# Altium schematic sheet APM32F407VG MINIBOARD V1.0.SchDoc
size A3; Organization: Altium Limited; Address1: 3 Minna Close; Address2: Belrose; Address3: NSW 2085; Address4: Australia; PageSetup: Record=PageOptions¦CenterHorizontal=True¦CenterVertical=True¦PrintScale=0.71¦XCorrection=1.00¦YCorrection=1.00¦PrintKind=0¦BorderSize=5000000¦LeftOffset=0¦BottomOffset=0¦Orientation=2¦PaperLength=1000¦PaperWidth=1000¦Scale=100¦PaperSource=7¦PrintQuality=-4¦MediaType=1¦DitherType=10¦PaperKind=A4¦PrintScaleMode=1
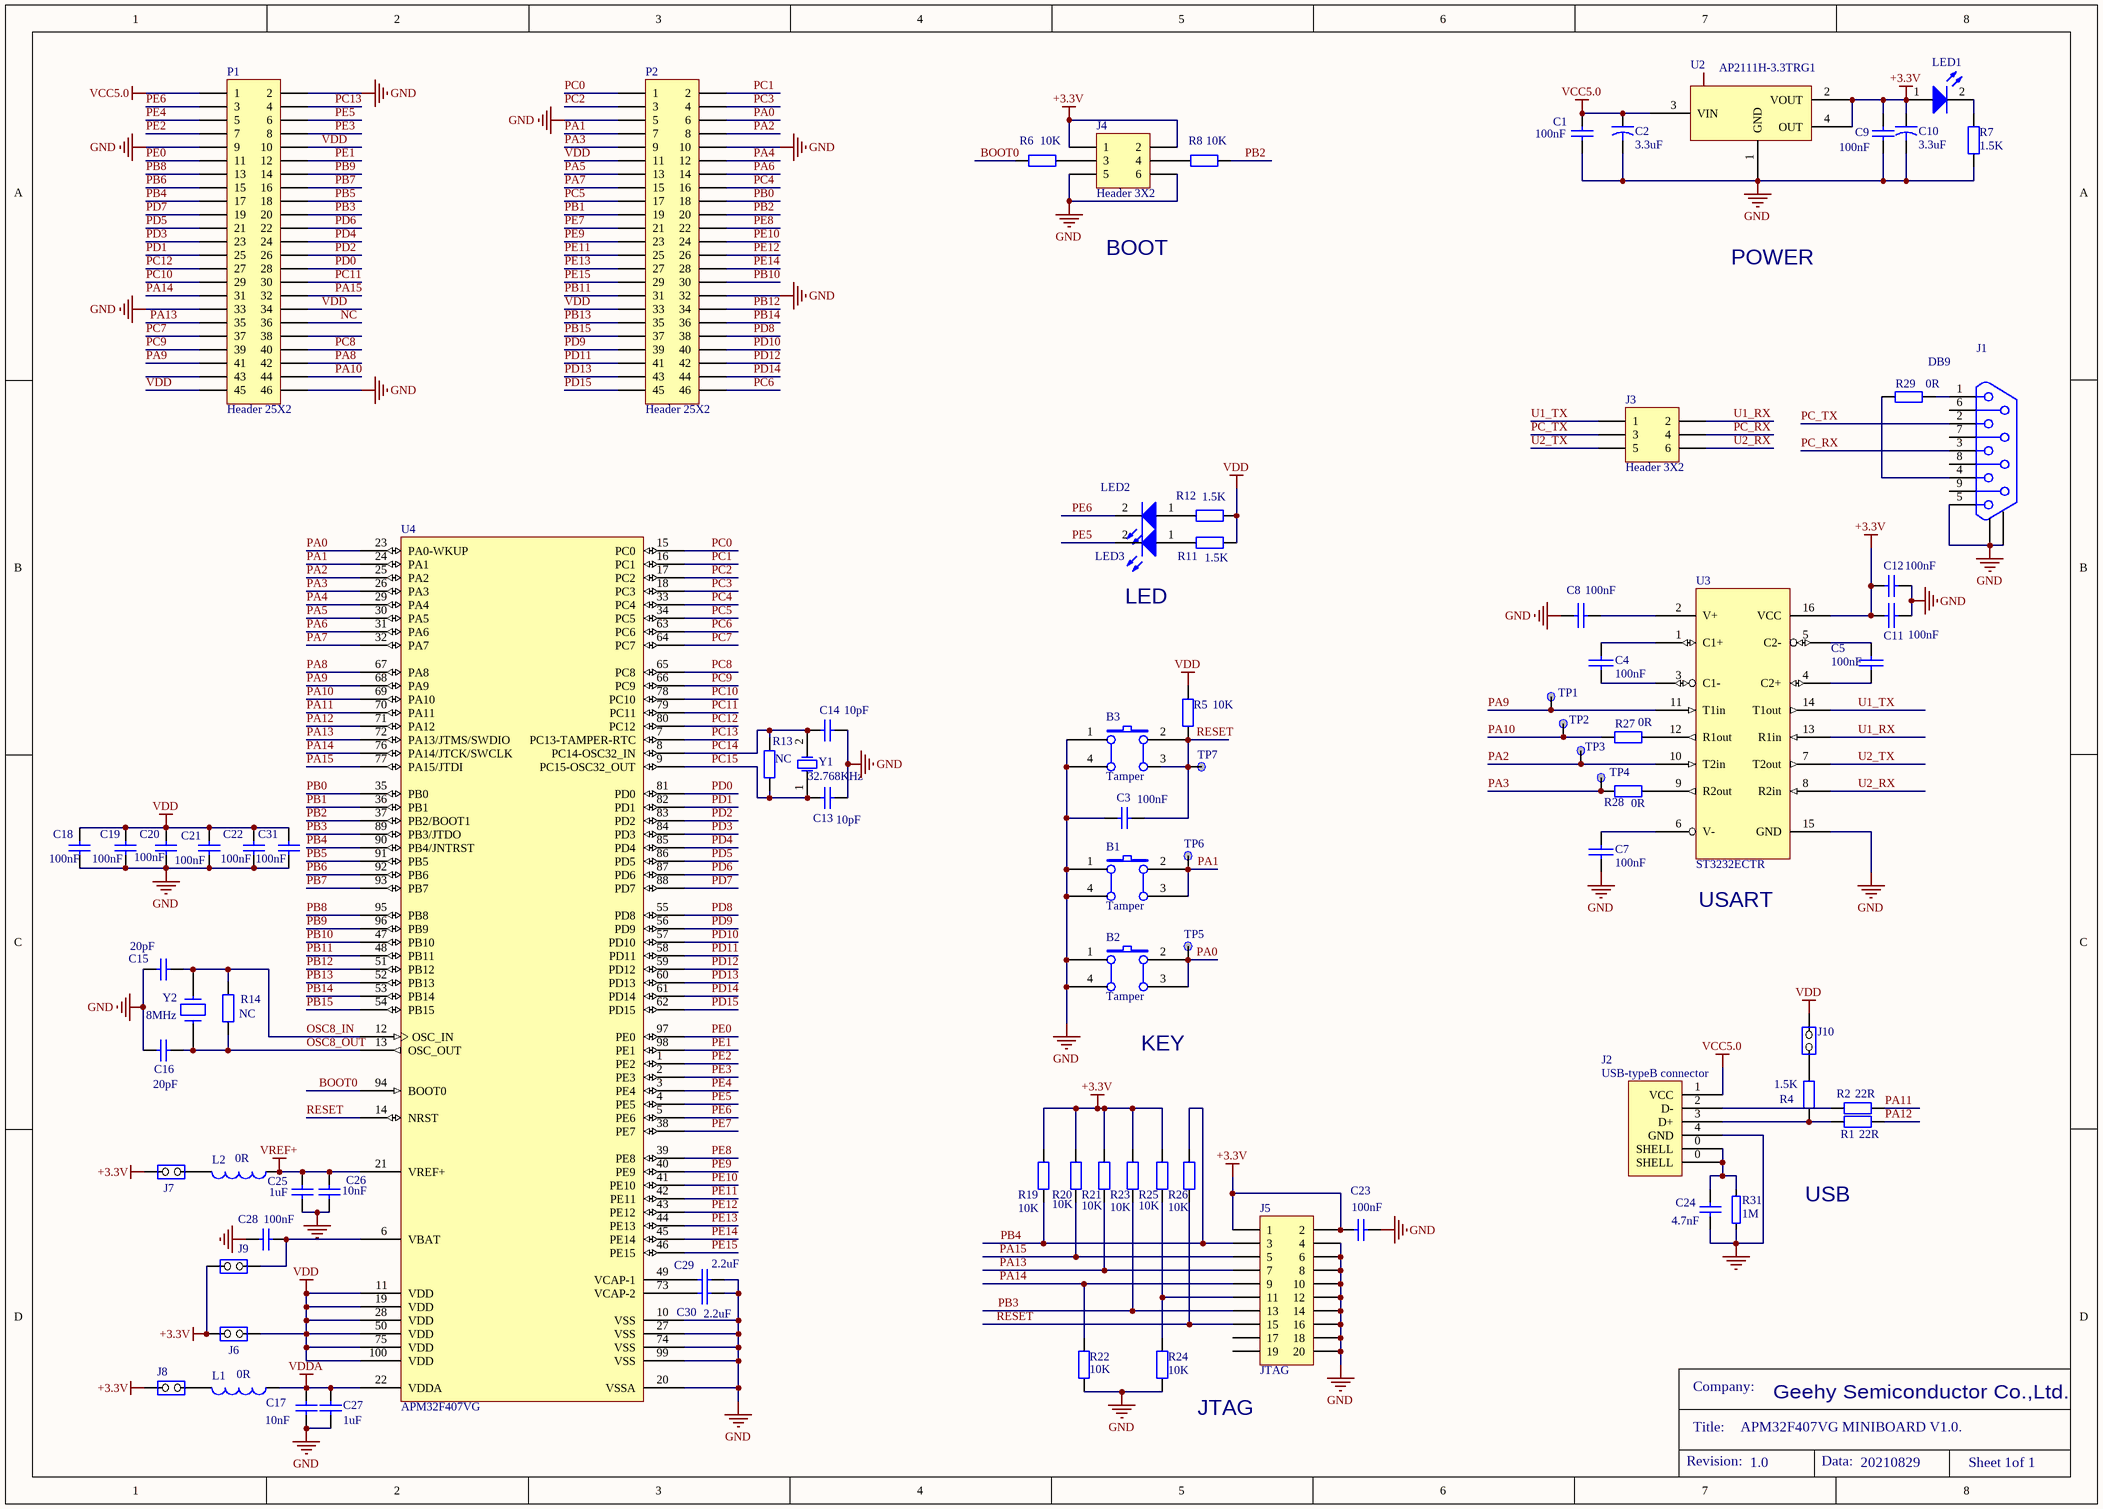
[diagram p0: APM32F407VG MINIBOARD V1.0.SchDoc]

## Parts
B1  Tamper  [PB10]
B2  Tamper  [PB10]
B3  Tamper  [PB10]
C1  100nF  [0603P]
C2  3.3uF  [TAN-B]
C3  100nF  [0603P]
C4  100nF  [0603P]
C5  100nF  [0603P]
C7  100nF  [0603P]
C8  100nF  [0603P]
C9  100nF  [0603P]
C10  3.3uF  [TAN-B]
C11  100nF  [0603P]
C12  100nF  [0603P]
C13  10pF  [0603P]
C14  10pF  [0603P]
C15  20pF  [0603P]
C16  20pF  [0603P]
C17  10nF  [0603P]
C18  100nF  [0603P]
C19  100nF  [0603P]
C20  100nF  [0603P]
C21  100nF  [0603P]
C22  100nF  [0603P]
C23  100nF  [0603P]
C24  4.7nF  [0603]
C25  1uF  [0603P]
C26  10nF  [0603P]
C27  1uF  [0603P]
C28  100nF  [0603P]
C29  2.2uF  [0603P]
C30  2.2uF  [0603P]
C31  100nF  [0603P]
J1  DB9  [DB9/F]
J2  USB-typeB connector  [USB-B]
J3  Header 3X2  [HDR2X3]
J4  Header 3X2  [HDR2X3]
J5  JTAG  [IDC20S]
J6  (no value)  [SIP2]
J7  (no value)  [SIP2]
J8  (no value)  [SIP2]
J9  (no value)  [SIP2]
J10  (no value)  [SIP2]
L1  0R  [0603]
L2  0R  [0603]
LED1  LED  [D0603]  (value not drawn)
LED2  LED  [D0603]  (value not drawn)
LED3  LED  [D0603]  (value not drawn)
P1  Header 25X2  [HDR2X23]
P2  Header 25X2  [HDR2X23]
R1  22R  [0603]
R2  22R  [0603]
R4  1.5K  [0603]
R5  10K  [0603]
R6  10K  [0603]
R7  1.5K  [0603]
R8  10K  [0603]
R11  1.5K  [0603]
R12  1.5K  [0603]
R13  NC  [0603]
R14  NC  [0603]
R19  10K  [0603]
R20  10K  [0603]
R21  10K  [0603]
R22  10K  [0603]
R23  10K  [0603]
R24  10K  [0603]
R25  10K  [0603]
R26  10K  [0603]
R27  0R  [0603]
R28  0R  [0603]
R29  0R  [0603]
R31  1M  [0603]
TP1  (no value)  [TP1.5]
TP2  (no value)  [TP1.5]
TP3  (no value)  [TP1.5]
TP4  (no value)  [TP1.5]
TP5  (no value)  [TP1.5]
TP6  (no value)  [TP1.5]
TP7  (no value)  [TP1.5]
U2  AP2111H-3.3TRG1  [SPX1117M]
U3  ST3232ECTR  [TSSOP16]
U4  APM32F407VG  [LQFP100_N]
Y1  32.768KHz  [R1206]
Y2  8MHz  [XTAL_socket]

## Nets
+3.3V: C9.2 C10.1 C11.1 C12.2 C23.2 J4.1 J4.2 J5.1 J5.2 J6.1(COMMON) J7.1(COMMON) J8.1(COMMON) J9.1(COMMON) LED1.1(A) R19.2 R20.2 R21.2 R23.2 R25.2 U2.2(VOUT) U2.4(OUT) U3.16(VCC)
GND: B1.1(A0) B1.4(A1) B2.1(A0) B2.4(A1) B3.1(A0) B3.4(A1) C1.1 C2.2 C3.1 C7.1 C8.1 C9.1 C10.2 C11.2 C12.1 C13.1 C14.1 C15.1 C16.1 C17.1 C18.1 C19.1 C20.1 C21.1 C22.1 C23.1 C24.1 C25.1 C26.1 C27.1 C28.1 C29.1 C30.1 C31.1 J1.0 J1.5 J2.4(GND) J4.5 J4.6 J5.4 J5.6 J5.8 J5.10 J5.12 J5.14 J5.16 J5.18 J5.20 P1.2 P1.9 P1.33 P1.46 P2.5 P2.10 P2.32 R7.1 R22.1 R24.1 R31.1 U2.1(GND) U3.15(GND) U4.10(VSS) U4.20(VSSA) U4.27(VSS) U4.74(VSS) U4.99(VSS)
VCC5.0: C1.2 C2.1 J2.1(VCC) P1.1 U2.3(VIN)
VDD: C18.2 C19.2 C20.2 C21.2 C22.2 C31.2 J6.2(NO) J10.1(COMMON) P1.10 P1.34 P1.45 P2.11 P2.33 R5.1 R11.1 R12.1 U4.11(VDD) U4.19(VDD) U4.28(VDD) U4.50(VDD) U4.75(VDD) U4.100(VDD)
VDDA: C17.2 C27.2 L1.1 U4.22(VDDA)
VREF+: C25.2 C26.2 L2.1 U4.21(VREF+)
BOOT0: R6.1 U4.94(BOOT0)
NC: P1.36
OSC8_IN: C15.2 R14.2 U4.12(OSC_IN) Y2.1
OSC8_OUT: C16.2 R14.1 U4.13(OSC_OUT) Y2.2
PA0: B2.2(B0) B2.3(B1) P2.6 TP5.1 U4.23(PA0-WKUP)
PA1: B1.2(B0) B1.3(B1) P2.7 TP6.1 U4.24(PA1)
PA2: P2.8 TP3.1 U3.10(T2in) U4.25(PA2)
PA3: P2.9 R28.1 TP4.1 U4.26(PA3)
PA4: P2.12 U4.29(PA4)
PA5: P2.13 U4.30(PA5)
PA6: P2.14 U4.31(PA6)
PA7: P2.15 U4.32(PA7)
PA8: P1.42 U4.67(PA8)
PA9: P1.41 TP1.1 U3.11(T1in) U4.68(PA9)
PA10: P1.44 R27.1 TP2.1 U4.69(PA10)
PA11: R2.2 U4.70(PA11)
PA12: R1.2 U4.71(PA12)
PA13: J5.7 P1.35 R21.1 U4.72(PA13/JTMS/SWDIO)
PA14: J5.9 P1.31 R22.2 U4.76(PA14/JTCK/SWCLK)
PA15: J5.5 P1.32 R20.1 U4.77(PA15/JTDI)
PB0: P2.18 U4.35(PB0)
PB1: P2.19 U4.36(PB1)
PB2: P2.20 R8.2 U4.37(PB2/BOOT1)
PB3: J5.13 P1.20 R23.1 U4.89(PB3/JTDO)
PB4: J5.3 P1.17 R19.1 R26.2 U4.90(PB4/JNTRST)
PB5: P1.18 U4.91(PB5)
PB6: P1.15 U4.92(PB6)
PB7: P1.16 U4.93(PB7)
PB8: P1.13 U4.95(PB8)
PB9: P1.14 U4.96(PB9)
PB10: P2.30 U4.47(PB10)
PB11: P2.31 U4.48(PB11)
PB12: P2.34 U4.51(PB12)
PB13: P2.35 U4.52(PB13)
PB14: P2.36 U4.53(PB14)
PB15: P2.37 U4.54(PB15)
PC0: P2.1 U4.15(PC0)
PC1: P2.2 U4.16(PC1)
PC2: P2.3 U4.17(PC2)
PC3: P2.4 U4.18(PC3)
PC4: P2.16 U4.33(PC4)
PC5: P2.17 U4.34(PC5)
PC6: P2.46 U4.63(PC6)
PC7: P1.37 U4.64(PC7)
PC8: P1.40 U4.65(PC8)
PC9: P1.39 U4.66(PC9)
PC10: P1.29 U4.78(PC10)
PC11: P1.30 U4.79(PC11)
PC12: P1.27 U4.80(PC12)
PC13: P1.4 U4.7(PC13-TAMPER-RTC)
PC14: C14.2 R13.1 U4.8(PC14-OSC32_IN) Y1.2(OSC2)
PC15: C13.2 R13.2 U4.9(PC15-OSC32_OUT) Y1.1(OSC1)
PC_RX: J1.3 J3.4
PC_TX: J1.2 J3.3
PD0: P1.28 U4.81(PD0)
PD1: P1.25 U4.82(PD1)
PD2: P1.26 U4.83(PD2)
PD3: P1.23 U4.84(PD3)
PD4: P1.24 U4.85(PD4)
PD5: P1.21 U4.86(PD5)
PD6: P1.22 U4.87(PD6)
PD7: P1.19 U4.88(PD7)
PD8: P2.38 U4.55(PD8)
PD9: P2.39 U4.56(PD9)
PD10: P2.40 U4.57(PD10)
PD11: P2.41 U4.58(PD11)
PD12: P2.42 U4.59(PD12)
PD13: P2.43 U4.60(PD13)
PD14: P2.44 U4.61(PD14)
PD15: P2.45 U4.62(PD15)
PE0: P1.11 U4.97(PE0)
PE1: P1.12 U4.98(PE1)
PE2: P1.7 U4.1(PE2)
PE3: P1.8 U4.2(PE3)
PE4: P1.5 U4.3(PE4)
PE5: LED3.2(K) P1.6 U4.4(PE5)
PE6: LED2.2(K) P1.3 U4.5(PE6)
PE7: P2.21 U4.38(PE7)
PE8: P2.22 U4.39(PE8)
PE9: P2.23 U4.40(PE9)
PE10: P2.24 U4.41(PE10)
PE11: P2.25 U4.42(PE11)
PE12: P2.26 U4.43(PE12)
PE13: P2.27 U4.44(PE13)
PE14: P2.28 U4.45(PE14)
PE15: P2.29 U4.46(PE15)
RESET: B3.2(B0) B3.3(B1) C3.2 J5.15 R5.2 R26.1 TP7.1 U4.14(NRST)
U1_RX: J3.2 U3.13(R1in)
U1_TX: J3.1 U3.14(T1out)
U2_RX: J3.6 U3.8(R2in)
U2_TX: J3.5 U3.7(T2out)
NetC4_1: C4.1 U3.1(C1+)
NetC4_2: C4.2 U3.3(C1-)
NetC5_1: C5.1 U3.4(C2+)
NetC5_2: C5.2 U3.5(C2-)
NetC7_2: C7.2 U3.6(V-)
NetC8_2: C8.2 U3.2(V+)
NetC24_2: C24.2 J2.0(SHELL) R31.2
NetC28_2: C28.2 J9.2(NO) U4.6(VBAT)
NetC29_2: C29.2 U4.49(VCAP-1)
NetC30_2: C30.2 U4.73(VCAP-2)
NetJ1_1: J1.1 R29.2
NetJ1_4: J1.4 R29.1
NetJ2_2: J2.2(D-) R2.1
NetJ2_3: J2.3(D+) R1.1 R4.1
NetJ4_3: J4.3 R6.2
NetJ4_4: J4.4 R8.1
NetJ5_11: J5.11 R24.2 R25.1
NetJ7_2: J7.2(NO) L2.2
NetJ8_2: J8.2(NO) L1.2
NetJ10_2: J10.2(NO) R4.2
NetLED1_2: LED1.2(K) R7.2
NetLED2_1: LED2.1(A) R12.2
NetLED3_1: LED3.1(A) R11.2
NetR27_2: R27.2 U3.12(R1out)
NetR28_2: R28.2 U3.9(R2out)

Not connected (* = marked no-connect by the designer): J1 6 7 8 9; J5 17 19; P1 38 43

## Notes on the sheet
- BOOT
- POWER
- LED
- USART
- (near B2) KEY
- USB
- Company:
- JTAG
- Title:
- APM32F407VG MINIBOARD V1.0.
- Geehy Semiconductor Co.,Ltd.
- Revision:
- 1.0
- Data:
- 20210829
- Sheet 1of 1

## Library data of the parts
B1-B3 = SW PUSHBUTTON: SE PUSHBUTTON
C1 C3 C9 C12 C17-C23 C25-C28 C31 = Cap: Capacitor; Value: 104
C2 C10 = Cap2: Capacitor; Value: 220uF
C4 C5 C7 C8 C11 = CAP: Capacitor
C13-C16 = Cap: Capacitor
C24 = CAP: Capacitor; Value: 100pF
C29 C30 = Cap: Capacitor; Value: 10pF
J2 = USB-B
J3 J4 = Header 3X2: Header, 3-Pin, Dual row
J5 = Header 10X2: Header, 10-Pin, Dual row
J6-J10 = JP2
L1 L2 = Inductor: Value: 100uH
LED1-LED3 = LED2: Typical RED, GREEN, YELLOW, AMBER GaAs LED
P1 P2 = Header 23X2: Header, 25-Pin, Dual row
R1 R4-R6 R8 R19-R26 = Res2: Resistor
R2 = Res2: Resistor; Value: 20
R7 R11 R12 = Res2: Resistor; Value: 470
R13 = Res2: Resistor; Value: 4.7K
R14 = Res2: Resistor; Value: 1M
R27-R29 = Res2: Resistor; Value: 1K
R31 = RES: '1/8W 5%; 描述: 5%/1/10W
TP1-TP7 = TP
U2 = SPX1117
U3 = ST3232: 3.3V/5V Dual RS232 Transceiver w/ Int. Cap.
Y1 = XTAL: Crystal Oscillator
Y2 = CRYSTAL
